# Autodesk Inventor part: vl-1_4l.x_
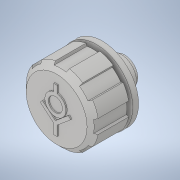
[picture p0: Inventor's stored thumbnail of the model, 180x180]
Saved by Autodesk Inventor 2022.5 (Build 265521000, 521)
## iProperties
Created: 2021-05
Part Number: vl-1_4l.x_
Material: 一般
Document SubType Name: Modeling
Designer: ImaoCorp
Density: 1 g/cm^3
Appearance: 既定
Sending System: SOLIDWORKS 2019-2019304
MC: AMD64
MC_MODEL: Intel64 Family 6 Model 60 Stepping 3, GenuineIntel
OS: Windows_NT
FRU: Parasolid Version 31.0, build 290,  9- 1-2019
FORMAT: text
GUISE: transmit
KEY: vl-1_4l
FILE: vl-1_4l.x_t
DATE: Wed May 19 16:42:56 2021
Author: ImaoCorp
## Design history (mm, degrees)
feature "Base1"
node "ソリッド1"
